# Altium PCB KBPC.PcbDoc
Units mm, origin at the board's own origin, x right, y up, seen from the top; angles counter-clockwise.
Board outline 29 x 29 mm, 2 copper layers (Top Layer, Bottom Layer); 0 components, 14 nets, 5 pads, 0 vias.
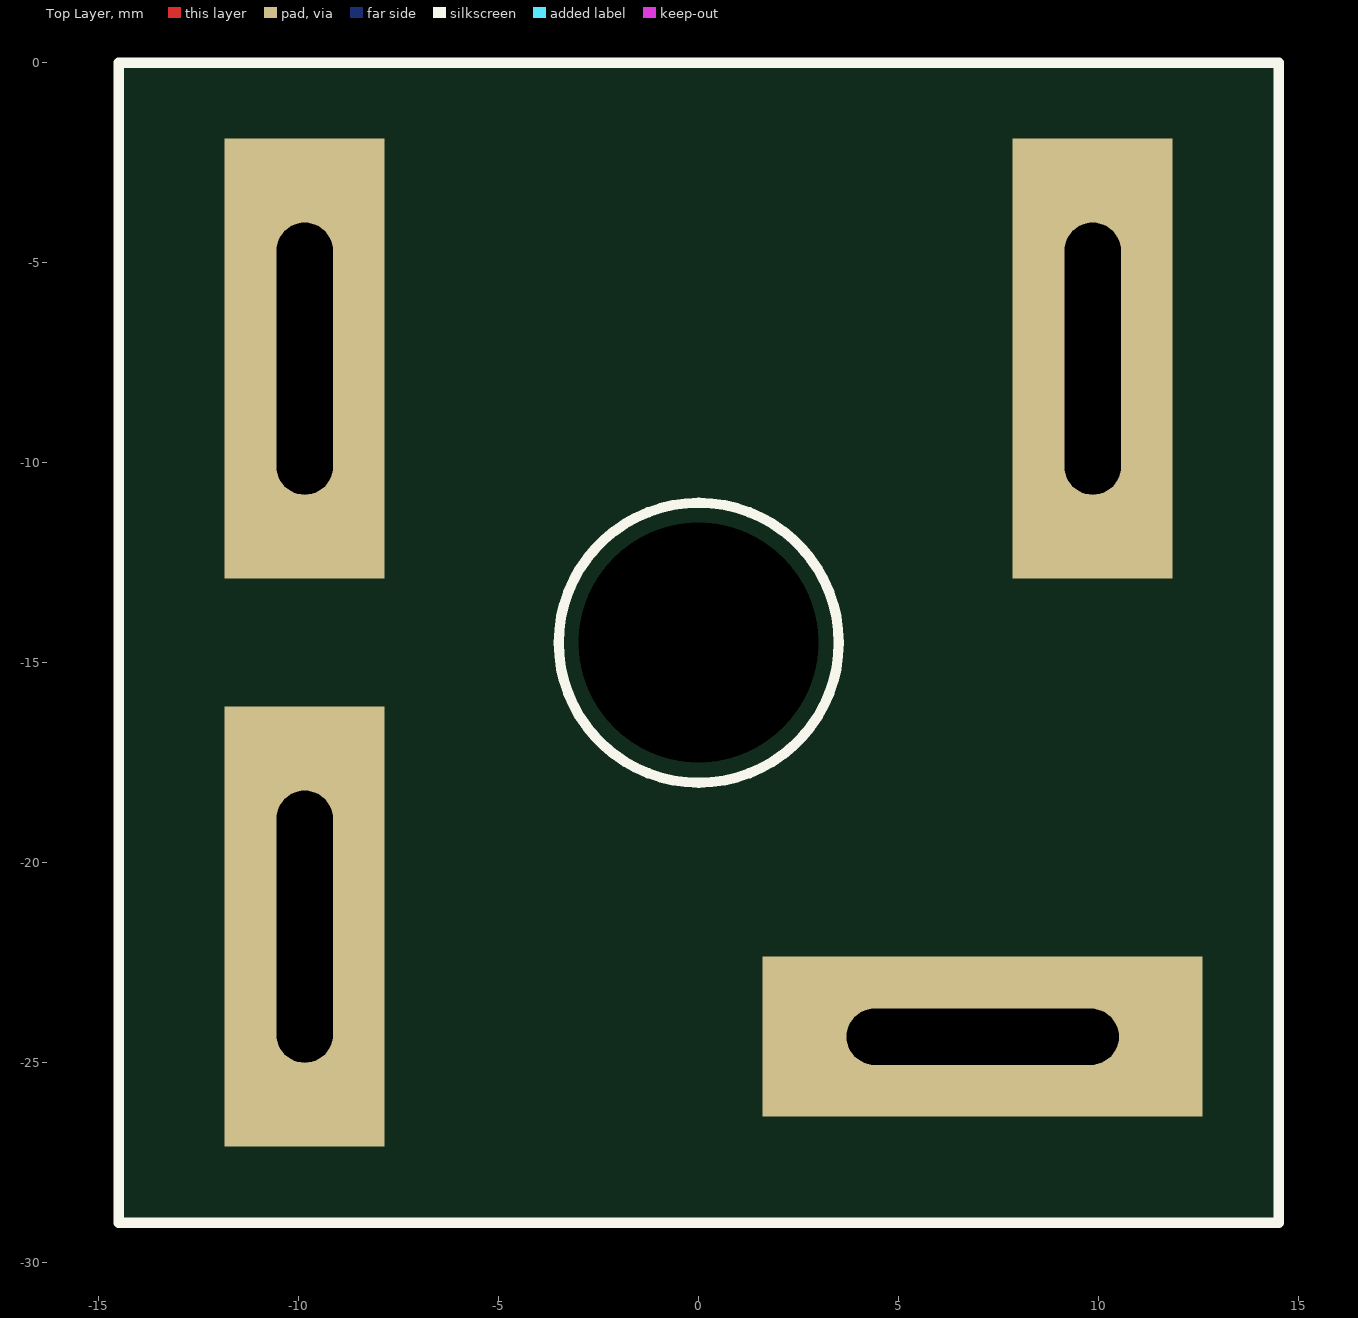
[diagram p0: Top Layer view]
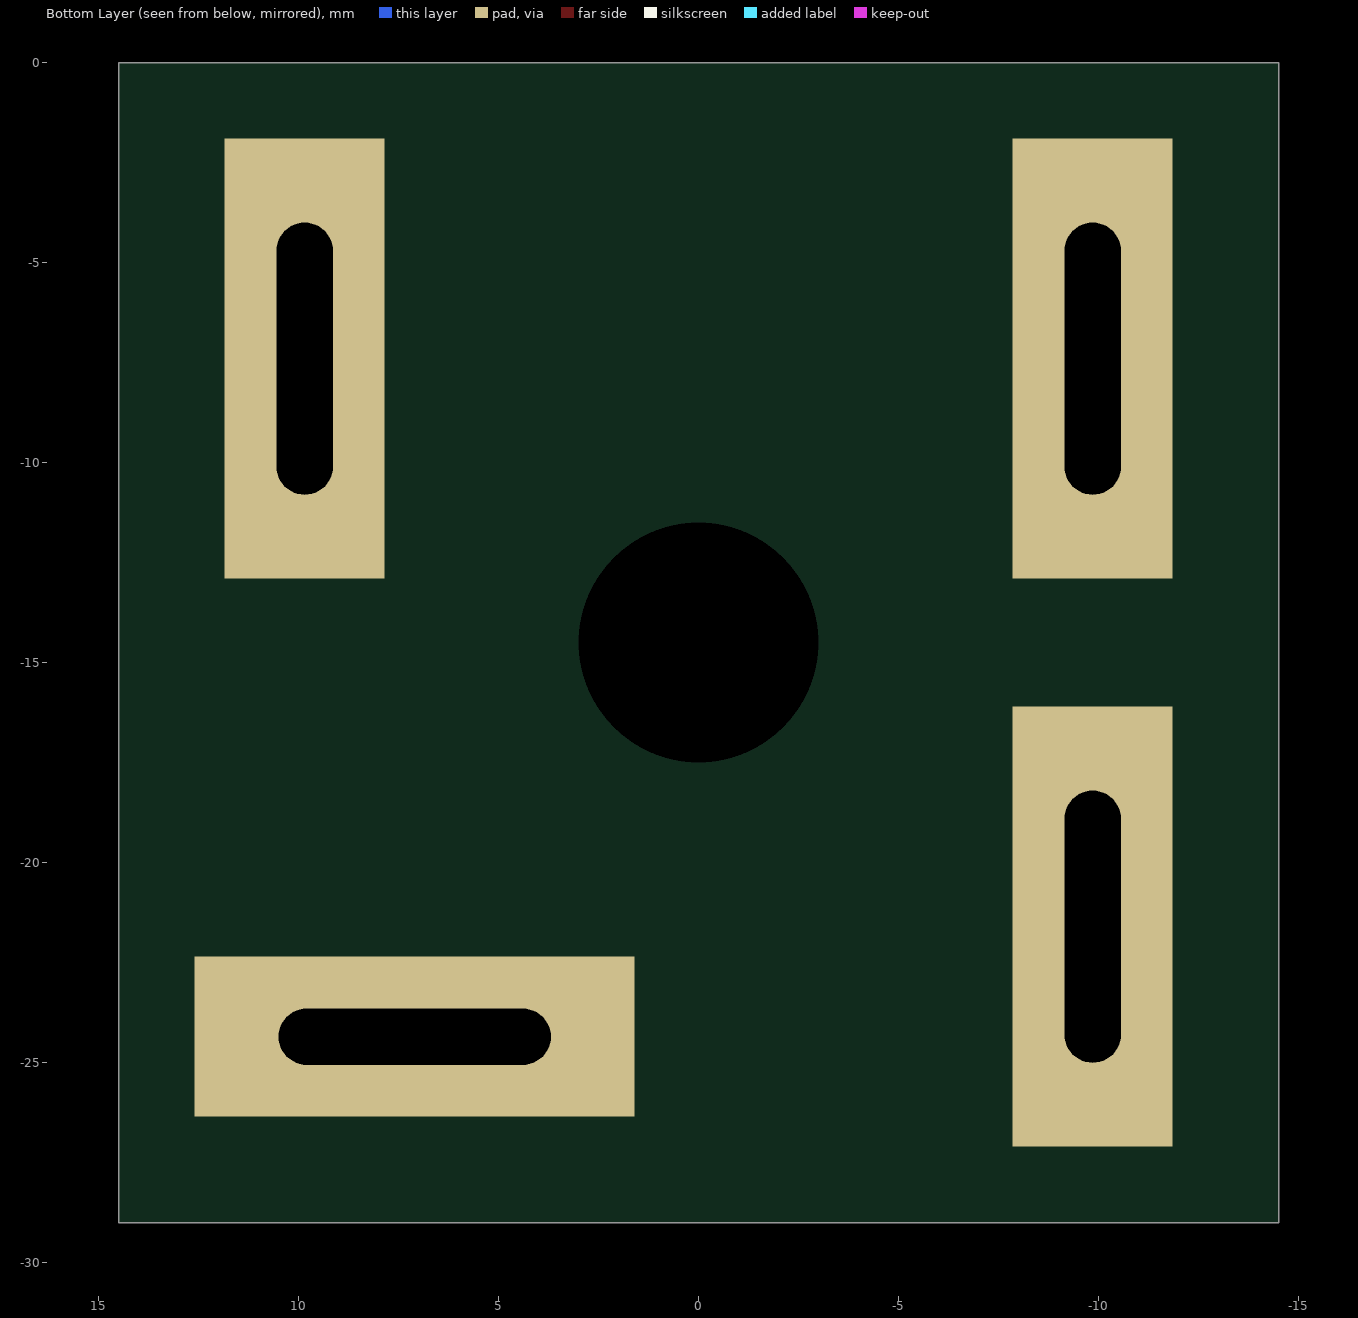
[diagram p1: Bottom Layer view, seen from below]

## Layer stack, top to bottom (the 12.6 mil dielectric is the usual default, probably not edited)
Top Layer: signal copper 0.0356
Dielectric: dielectric 0.32, FR-4, Dk 4.8
Bottom Layer: signal copper 0.0356

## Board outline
-14.5,-29 -14.5,0 14.5,0 14.5,-29

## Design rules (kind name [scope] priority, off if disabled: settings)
Clearance [All] p1: gap=0.254
PolygonConnect [All] p1: connectstyle=Relief reliefconductorwidth=0.254 reliefentries=4 polygonreliefangle="90 Angle"
RoutingVias [All] p1: holewidth=0.711 width=1.27 viastyle="Through Hole" minholewidth=0.711 minwidth=1.27 maxholewidth=0.711 maxwidth=1.27
SilkscreenOverComponentPads [All] p1: minsilkscreentomaskgap=0.254
SolderMaskExpansion [All] p1: expansion=0.102
Width [All] p1: maxlimit=3 minlimit=0.254 preferedwidth=0.254 minimp=50.000000 maximp=50.000000 favimp=50.000000
27 further rules are at their usual default settings.

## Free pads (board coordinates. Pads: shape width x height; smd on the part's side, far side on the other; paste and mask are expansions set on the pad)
  round 0 hole 6: 0(0,-14.5)
  rect 11x4 hole 1.4 slot 6.8 at 0 deg: 1(7.1,-24.35)
  rect 4x11 hole 1.4 slot 6.8 at 90 deg: 2(-9.85,-7.4) 4(9.85,-7.4) 6(-9.85,-21.6)

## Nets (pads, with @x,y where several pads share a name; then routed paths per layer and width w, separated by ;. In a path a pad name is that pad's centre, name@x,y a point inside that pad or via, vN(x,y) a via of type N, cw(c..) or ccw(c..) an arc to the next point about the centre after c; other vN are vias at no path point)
GND: 
NetC3_2: 
NetC5_1: 
NetCFF_2: 
NetD1_2: 
NetL1_1: 
NetL2_2: 
NetMC2_10: 
V: 
VAUX: 
VAUX2: 
VCELL: 
VOUT: 
VOUT2: 

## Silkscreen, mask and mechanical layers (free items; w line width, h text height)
Top Overlay:
  circle w0.254: c0,-14.5 r3.5
  lines w0.254: -14.5,-29 -14.5,0 14.5,0 14.5,-29 -14.5,-29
